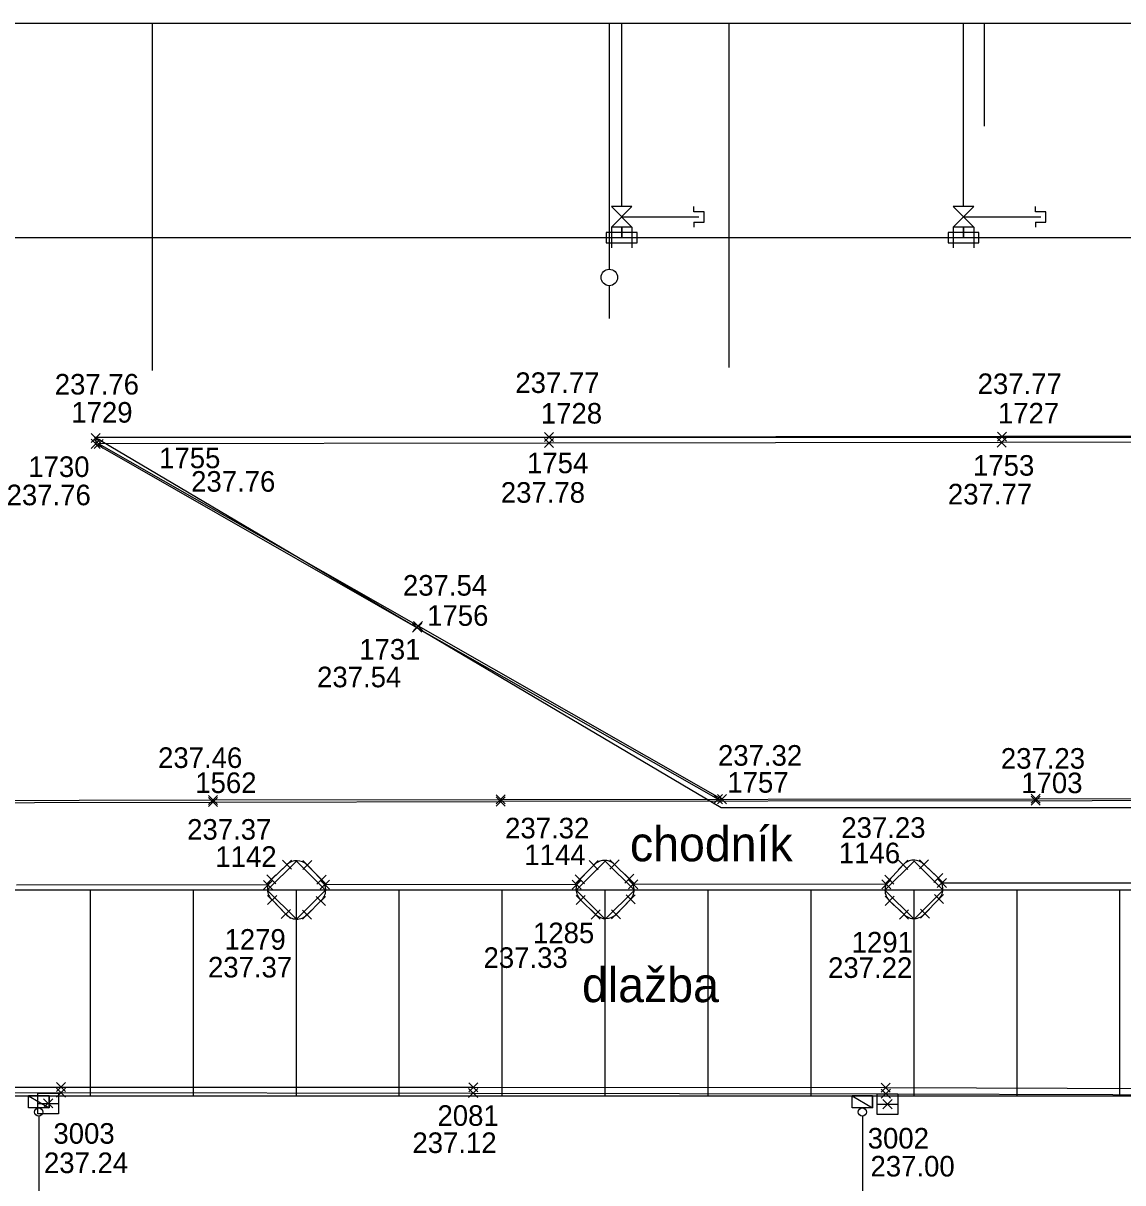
# Model space of a CAD drawing. Extents: x -264165 to -263733, y -1242319 to -1242245.
# Drawn here: x -263851.2 to -263824.5, y -1242273.09 to -1242244.94 of the extents above; entities that cross this region are included whole.
import ezdxf

# ---------------------------------------------------------------- set-up
doc = ezdxf.new("R2010")
doc.units = 0
for name, color, linetype in [('KFA_BOD_CISLO', 7, 'Continuous'), ('KFA_BOD_SYMBOL', 7, 'Continuous'), ('KFA_BOD_VYSKA', 7, 'Continuous'), ('KFA_SO_20-2_OBRUBNIKY_DOLNA_HRANA', 7, 'Continuous'), ('KFA_SO_20-2_OBRUBNIKY_HORNA_HRANA', 7, 'Continuous'), ('KFA_UV_BOD_CISLO', 7, 'Continuous'), ('KFA_UV_BOD_SYMBOL', 7, 'Continuous'), ('KFA_UV_BOD_VYSKA', 7, 'Continuous'), ('POPIS', 7, 'Continuous'), ('PROJEKT_OBRUBNIKY_KOMUNIKACIE', 7, 'Continuous'), ('PROJEKT_TDZ_VODOROVNE', 7, 'Continuous'), ('RAM_NA_TLAC_1-250', 7, 'Continuous'), ('SITUACIA_DSP_2D', 7, 'Continuous'), ('ULICNA_VPUST_POKLOP', 7, 'Continuous')]:
    doc.layers.add(name, color=color, linetype=linetype)

msp = doc.modelspace()

# ---------------------------------------------------------------- linework, layer by layer
at = {"layer": 'KFA_BOD_SYMBOL'}
for p, q in [((-263849.55, -1242255.261), (-263849.329, -1242255.039)), ((-263849.329, -1242255.261), (-263849.55, -1242255.039)), ((-263849.549, -1242255.116), (-263849.328, -1242254.894)), ((-263849.328, -1242255.116), (-263849.549, -1242254.894)), ((-263849.478, -1242255.262), (-263849.257, -1242255.042)), ((-263849.257, -1242255.262), (-263849.478, -1242255.042)), ((-263838.542, -1242255.093), (-263838.321, -1242254.873)), ((-263838.321, -1242255.093), (-263838.542, -1242254.873)), ((-263838.542, -1242255.241), (-263838.321, -1242255.019)), ((-263838.321, -1242255.241), (-263838.542, -1242255.019)), ((-263827.55, -1242255.228), (-263827.329, -1242255.007)), ((-263827.329, -1242255.228), (-263827.55, -1242255.007)), ((-263827.542, -1242255.083), (-263827.321, -1242254.862)), ((-263827.321, -1242255.083), (-263827.542, -1242254.862)), ((-263841.745, -1242259.725), (-263841.524, -1242259.504)), ((-263841.524, -1242259.725), (-263841.745, -1242259.504)), ((-263841.725, -1242259.681), (-263841.503, -1242259.461)), ((-263841.503, -1242259.681), (-263841.725, -1242259.461)), ((-263846.704, -1242263.907), (-263846.483, -1242263.687)), ((-263846.483, -1242263.907), (-263846.704, -1242263.687)), ((-263846.704, -1242263.958), (-263846.483, -1242263.737)), ((-263846.483, -1242263.958), (-263846.704, -1242263.737)), ((-263839.718, -1242263.894), (-263839.497, -1242263.674)), ((-263839.497, -1242263.894), (-263839.718, -1242263.674)), ((-263839.718, -1242263.944), (-263839.497, -1242263.724)), ((-263839.497, -1242263.944), (-263839.718, -1242263.724)), ((-263834.438, -1242263.887), (-263834.217, -1242263.666)), ((-263834.217, -1242263.887), (-263834.438, -1242263.666)), ((-263834.345, -1242263.887), (-263834.125, -1242263.666)), ((-263834.125, -1242263.887), (-263834.345, -1242263.666)), ((-263826.729, -1242263.924), (-263826.508, -1242263.704)), ((-263826.508, -1242263.924), (-263826.729, -1242263.704)), ((-263826.726, -1242263.876), (-263826.505, -1242263.654)), ((-263826.505, -1242263.876), (-263826.726, -1242263.654)), ((-263844.905, -1242265.475), (-263844.684, -1242265.255)), ((-263844.684, -1242265.475), (-263844.905, -1242265.255)), ((-263844.414, -1242265.488), (-263844.193, -1242265.266)), ((-263844.193, -1242265.488), (-263844.414, -1242265.266)), ((-263837.459, -1242265.49), (-263837.237, -1242265.269)), ((-263837.237, -1242265.49), (-263837.459, -1242265.269)), ((-263836.953, -1242265.474), (-263836.731, -1242265.252)), ((-263836.731, -1242265.474), (-263836.953, -1242265.252)), ((-263829.944, -1242265.481), (-263829.723, -1242265.261)), ((-263829.723, -1242265.481), (-263829.944, -1242265.261)), ((-263829.438, -1242265.471), (-263829.216, -1242265.251)), ((-263829.216, -1242265.471), (-263829.438, -1242265.251)), ((-263845.365, -1242265.968), (-263845.144, -1242265.748)), ((-263845.144, -1242265.968), (-263845.365, -1242265.748)), ((-263845.285, -1242265.836), (-263845.063, -1242265.615)), ((-263845.063, -1242265.836), (-263845.285, -1242265.615)), ((-263844.067, -1242265.84), (-263843.845, -1242265.619)), ((-263843.845, -1242265.84), (-263844.067, -1242265.619)), ((-263843.986, -1242265.965), (-263843.765, -1242265.745)), ((-263843.765, -1242265.965), (-263843.986, -1242265.745)), ((-263837.871, -1242265.961), (-263837.649, -1242265.741)), ((-263837.649, -1242265.961), (-263837.871, -1242265.741)), ((-263837.795, -1242265.833), (-263837.573, -1242265.613)), ((-263837.573, -1242265.833), (-263837.795, -1242265.613)), ((-263836.594, -1242265.819), (-263836.372, -1242265.599)), ((-263836.372, -1242265.819), (-263836.594, -1242265.599)), ((-263836.501, -1242265.958), (-263836.28, -1242265.738)), ((-263836.28, -1242265.958), (-263836.501, -1242265.738)), ((-263830.355, -1242265.954), (-263830.133, -1242265.732)), ((-263830.133, -1242265.954), (-263830.355, -1242265.732)), ((-263830.278, -1242265.843), (-263830.057, -1242265.622)), ((-263830.057, -1242265.843), (-263830.278, -1242265.622)), ((-263829.092, -1242265.799), (-263828.871, -1242265.578)), ((-263828.871, -1242265.799), (-263829.092, -1242265.578)), ((-263829.004, -1242265.924), (-263828.783, -1242265.704)), ((-263828.783, -1242265.924), (-263829.004, -1242265.704)), ((-263845.267, -1242266.335), (-263845.046, -1242266.113)), ((-263845.046, -1242266.335), (-263845.267, -1242266.113)), ((-263844.085, -1242266.357), (-263843.864, -1242266.137)), ((-263843.864, -1242266.357), (-263844.085, -1242266.137)), ((-263837.775, -1242266.333), (-263837.554, -1242266.113)), ((-263837.554, -1242266.333), (-263837.775, -1242266.113)), ((-263836.56, -1242266.319), (-263836.339, -1242266.097)), ((-263836.339, -1242266.319), (-263836.56, -1242266.097)), ((-263830.274, -1242266.356), (-263830.052, -1242266.134)), ((-263830.052, -1242266.356), (-263830.274, -1242266.134)), ((-263829.074, -1242266.312), (-263828.853, -1242266.09)), ((-263828.853, -1242266.312), (-263829.074, -1242266.09)), ((-263844.933, -1242266.678), (-263844.712, -1242266.458)), ((-263844.712, -1242266.678), (-263844.933, -1242266.458)), ((-263844.42, -1242266.693), (-263844.198, -1242266.471)), ((-263844.198, -1242266.693), (-263844.42, -1242266.471)), ((-263837.41, -1242266.688), (-263837.189, -1242266.468)), ((-263837.189, -1242266.688), (-263837.41, -1242266.468)), ((-263836.916, -1242266.684), (-263836.695, -1242266.464)), ((-263836.695, -1242266.684), (-263836.916, -1242266.464)), ((-263829.922, -1242266.687), (-263829.701, -1242266.465)), ((-263829.701, -1242266.687), (-263829.922, -1242266.465)), ((-263829.414, -1242266.664), (-263829.193, -1242266.444)), ((-263829.193, -1242266.664), (-263829.414, -1242266.444)), ((-263850.395, -1242271.014), (-263850.174, -1242270.792)), ((-263850.174, -1242271.014), (-263850.395, -1242270.792)), ((-263850.392, -1242270.877), (-263850.171, -1242270.656)), ((-263850.171, -1242270.877), (-263850.392, -1242270.656)), ((-263840.384, -1242271.024), (-263840.163, -1242270.802)), ((-263840.163, -1242271.024), (-263840.384, -1242270.802)), ((-263840.382, -1242270.883), (-263840.16, -1242270.661)), ((-263840.16, -1242270.883), (-263840.382, -1242270.661)), ((-263830.367, -1242270.893), (-263830.145, -1242270.671)), ((-263830.145, -1242270.893), (-263830.367, -1242270.671)), ((-263830.365, -1242271.039), (-263830.144, -1242270.819)), ((-263830.144, -1242271.039), (-263830.365, -1242270.819))]:
    msp.add_line(p, q, dxfattribs=at)
at = {"layer": 'KFA_SO_20-2_OBRUBNIKY_DOLNA_HRANA'}
for points in [[(-263870.268, -1242270.778), (-263860.244, -1242270.766), (-263850.281, -1242270.766), (-263840.271, -1242270.772), (-263830.256, -1242270.782), (-263819.239, -1242270.817)], [(-263870.27, -1242270.923), (-263860.247, -1242270.914), (-263850.285, -1242270.903), (-263840.274, -1242270.913), (-263830.254, -1242270.929), (-263819.233, -1242270.965)]]:
    msp.add_lwpolyline(points, dxfattribs=at)
at = {"layer": 'KFA_SO_20-2_OBRUBNIKY_HORNA_HRANA'}
for p, q in [((-263839.607, -1242263.784), (-263826.616, -1242263.765)), ((-263826.616, -1242263.765), (-263822.618, -1242263.754)), ((-263826.618, -1242263.814), (-263839.607, -1242263.834)), ((-263826.618, -1242263.814), (-263822.617, -1242263.795)), ((-263845.174, -1242265.725), (-263844.795, -1242265.365)), ((-263844.303, -1242265.377), (-263843.956, -1242265.729)), ((-263837.684, -1242265.723), (-263837.348, -1242265.379)), ((-263836.483, -1242265.709), (-263836.842, -1242265.363)), ((-263830.167, -1242265.732), (-263829.834, -1242265.371)), ((-263829.327, -1242265.361), (-263828.981, -1242265.688)), ((-263845.254, -1242265.858), (-263851.364, -1242265.868)), ((-263837.76, -1242265.851), (-263843.876, -1242265.855)), ((-263830.244, -1242265.843), (-263836.39, -1242265.848)), ((-263822.6, -1242265.815), (-263828.894, -1242265.814)), ((-263844.823, -1242266.568), (-263845.156, -1242266.224)), ((-263843.975, -1242266.247), (-263844.309, -1242266.582)), ((-263837.665, -1242266.223), (-263837.3, -1242266.578)), ((-263836.806, -1242266.574), (-263836.449, -1242266.208)), ((-263829.812, -1242266.576), (-263830.163, -1242266.245)), ((-263828.964, -1242266.201), (-263829.303, -1242266.554))]:
    msp.add_line(p, q, dxfattribs=at)
for points in [[(-263802.049, -1242254.926), (-263813.428, -1242254.951), (-263827.432, -1242254.972), (-263838.432, -1242254.983), (-263849.438, -1242255.005), (-263849.439, -1242255.15), (-263841.634, -1242259.614), (-263834.328, -1242263.776)], [(-263802.192, -1242255.074), (-263813.429, -1242255.098), (-263827.439, -1242255.117), (-263838.432, -1242255.13), (-263849.367, -1242255.152), (-263841.614, -1242259.571), (-263834.235, -1242263.776)], [(-263909.527, -1242263.897), (-263899.537, -1242263.895), (-263889.544, -1242263.882), (-263879.556, -1242263.864), (-263869.563, -1242263.857), (-263859.593, -1242263.827), (-263846.594, -1242263.797), (-263839.607, -1242263.784)], [(-263909.527, -1242263.947), (-263899.537, -1242263.945), (-263889.544, -1242263.932), (-263879.556, -1242263.914), (-263869.563, -1242263.907), (-263859.593, -1242263.877), (-263846.594, -1242263.847), (-263839.607, -1242263.834)]]:
    msp.add_lwpolyline(points, dxfattribs=at)
for centre, major_axis, ratio, start_param, end_param in [((-263844.555, -1242265.625), (-0.353, 0.033), 0.998197, 4.012394, 5.547908), ((-263837.087, -1242265.615), (-0.326, -0.134), 0.999936, 3.551655, 5.156884), ((-263829.576, -1242265.607), (-0.346, 0.052), 0.998302, 4.072697, 5.692261), ((-263844.925, -1242265.966), (-0.275, -0.211), 0.999634, 4.858507, 6.470204), ((-263844.209, -1242265.979), (0.065, 0.35), 0.999654, 4.043218, 5.6761), ((-263837.425, -1242265.964), (0.248, -0.252), 0.999842, 3.187032, 4.758259), ((-263836.732, -1242265.977), (-0.155, 0.331), 0.999985, 3.589625, 5.096185), ((-263829.918, -1242265.987), (-0.226, -0.276), 0.999926, 4.603012, 6.210751), ((-263829.231, -1242265.953), (-0.033, 0.363), 0.99945, 3.87257, 5.43466), ((-263844.56, -1242266.343), (0.151, 0.311), 0.999672, 2.729443, 4.403752), ((-263837.055, -1242266.322), (0.263, 0.238), 0.999704, 3.213048, 4.755576), ((-263829.568, -1242266.325), (0.35, 0.015), 0.999834, 3.897217, 5.527561)]:
    msp.add_ellipse(centre, major_axis=major_axis, ratio=ratio, start_param=start_param, end_param=end_param, dxfattribs=at)
at = {"layer": 'KFA_UV_BOD_SYMBOL'}
for p, q in [((-263850.704, -1242271.275), (-263850.483, -1242271.053)), ((-263850.483, -1242271.275), (-263850.704, -1242271.053)), ((-263830.324, -1242271.293), (-263830.103, -1242271.073)), ((-263830.103, -1242271.293), (-263830.324, -1242271.073))]:
    msp.add_line(p, q, dxfattribs=at)
at = {"layer": 'PROJEKT_OBRUBNIKY_KOMUNIKACIE'}
for p, q in [((-263807.068, -1242265.987), (-263917.08, -1242265.983)), ((-263917.578, -1242270.983), (-263807.068, -1242270.982))]:
    msp.add_line(p, q, dxfattribs=at)
for points in [[(-263802.068, -1242263.988), (-263834.256, -1242263.984), (-263849.468, -1242254.985), (-263802.068, -1242254.987), (-263802.068, -1242263.988)], [(-263844.568, -1242265.279), (-263843.861, -1242265.986), (-263844.568, -1242266.694), (-263845.275, -1242265.986), (-263844.568, -1242265.279)], [(-263837.068, -1242265.279), (-263836.361, -1242265.986), (-263837.068, -1242266.694), (-263837.775, -1242265.986), (-263837.068, -1242265.279)], [(-263829.568, -1242265.279), (-263828.861, -1242265.986), (-263829.568, -1242266.694), (-263830.275, -1242265.986), (-263829.568, -1242265.279)]]:
    msp.add_lwpolyline(points, dxfattribs=at)
at = {"layer": 'PROJEKT_TDZ_VODOROVNE'}
for p, q in [((-263849.568, -1242270.982), (-263849.568, -1242265.982)), ((-263847.068, -1242270.982), (-263847.068, -1242265.982)), ((-263844.568, -1242270.982), (-263844.568, -1242265.982)), ((-263842.068, -1242270.982), (-263842.068, -1242265.982)), ((-263839.568, -1242270.982), (-263839.568, -1242265.982)), ((-263837.068, -1242270.982), (-263837.068, -1242265.982)), ((-263834.568, -1242270.982), (-263834.568, -1242265.982)), ((-263832.068, -1242270.982), (-263832.068, -1242265.982)), ((-263829.568, -1242270.982), (-263829.568, -1242265.982)), ((-263827.068, -1242270.982), (-263827.068, -1242265.982)), ((-263824.568, -1242270.982), (-263824.568, -1242265.982))]:
    msp.add_line(p, q, dxfattribs=at)
at = {"layer": 'RAM_NA_TLAC_1-250'}
msp.add_line((-263827.863, -1242244.935), (-263827.863, -1242247.435), dxfattribs=at)
msp.add_lwpolyline([(-264165.363, -1242244.935), (-263732.863, -1242244.935), (-263732.863, -1242319.185), (-264165.363, -1242319.185)], close=True, dxfattribs=at)
at = {"layer": 'SITUACIA_DSP_2D'}
for p, q in [((-263848.068, -1242244.935), (-263848.068, -1242253.366)), ((-263836.969, -1242244.935), (-263836.969, -1242250.909)), ((-263836.668, -1242249.39), (-263836.668, -1242244.935)), ((-263834.068, -1242244.935), (-263834.068, -1242253.298)), ((-263828.368, -1242249.39), (-263828.368, -1242244.935)), ((-263836.418, -1242249.39), (-263836.918, -1242249.39)), ((-263836.918, -1242249.89), (-263836.418, -1242249.39)), ((-263836.918, -1242249.39), (-263836.418, -1242249.89)), ((-263834.918, -1242249.515), (-263834.918, -1242249.39)), ((-263828.118, -1242249.39), (-263828.618, -1242249.39)), ((-263828.618, -1242249.89), (-263828.118, -1242249.39)), ((-263828.618, -1242249.39), (-263828.118, -1242249.89)), ((-263826.618, -1242249.515), (-263826.618, -1242249.39)), ((-263836.668, -1242249.64), (-263834.793, -1242249.64)), ((-263834.668, -1242249.515), (-263834.918, -1242249.515)), ((-263834.668, -1242249.765), (-263834.668, -1242249.515)), ((-263828.368, -1242249.64), (-263826.493, -1242249.64)), ((-263826.368, -1242249.515), (-263826.618, -1242249.515)), ((-263826.368, -1242249.765), (-263826.368, -1242249.515)), ((-263836.418, -1242249.89), (-263836.918, -1242249.89)), ((-263836.918, -1242249.89), (-263836.918, -1242250.39)), ((-263836.668, -1242250.14), (-263836.668, -1242249.89)), ((-263836.668, -1242249.89), (-263836.668, -1242250.14)), ((-263836.418, -1242249.89), (-263836.418, -1242250.39)), ((-263834.918, -1242249.765), (-263834.918, -1242249.89)), ((-263834.918, -1242249.765), (-263834.668, -1242249.765)), ((-263828.118, -1242249.89), (-263828.618, -1242249.89)), ((-263828.618, -1242249.89), (-263828.618, -1242250.39)), ((-263828.368, -1242250.14), (-263828.368, -1242249.89)), ((-263828.368, -1242249.89), (-263828.368, -1242250.14)), ((-263828.118, -1242249.89), (-263828.118, -1242250.39)), ((-263826.618, -1242249.765), (-263826.618, -1242249.89)), ((-263826.618, -1242249.765), (-263826.368, -1242249.765)), ((-263924.143, -1242250.14), (-263788.143, -1242250.14)), ((-263836.293, -1242250.015), (-263837.043, -1242250.015)), ((-263837.043, -1242250.015), (-263837.043, -1242250.265)), ((-263837.043, -1242250.265), (-263836.293, -1242250.265)), ((-263836.293, -1242250.265), (-263836.293, -1242250.015)), ((-263827.993, -1242250.015), (-263828.743, -1242250.015)), ((-263828.743, -1242250.015), (-263828.743, -1242250.265)), ((-263828.743, -1242250.265), (-263827.993, -1242250.265)), ((-263827.993, -1242250.265), (-263827.993, -1242250.015)), ((-263836.969, -1242251.309), (-263836.969, -1242252.109)), ((-263851.074, -1242270.983), (-263850.574, -1242270.983)), ((-263851.074, -1242271.273), (-263851.074, -1242270.983)), ((-263851.074, -1242270.983), (-263850.574, -1242271.273)), ((-263851.074, -1242270.983), (-263850.574, -1242271.273)), ((-263850.574, -1242270.983), (-263851.074, -1242270.983)), ((-263850.574, -1242270.983), (-263850.574, -1242271.273)), ((-263850.574, -1242271.273), (-263850.574, -1242270.983)), ((-263831.074, -1242270.983), (-263830.574, -1242270.983)), ((-263831.074, -1242271.273), (-263831.074, -1242270.983)), ((-263831.074, -1242270.983), (-263830.574, -1242271.273)), ((-263831.074, -1242270.983), (-263830.574, -1242271.273)), ((-263830.574, -1242270.983), (-263831.074, -1242270.983)), ((-263830.574, -1242270.983), (-263830.574, -1242271.273)), ((-263830.574, -1242271.273), (-263830.574, -1242270.983)), ((-263850.574, -1242271.273), (-263851.074, -1242271.273)), ((-263830.574, -1242271.273), (-263831.074, -1242271.273)), ((-263850.824, -1242271.473), (-263850.824, -1242283.187)), ((-263830.824, -1242271.473), (-263830.824, -1242283.187))]:
    msp.add_line(p, q, dxfattribs=at)
for points in [[(-263802.068, -1242263.988), (-263834.256, -1242263.984), (-263849.468, -1242254.985), (-263802.068, -1242254.987)], [(-263844.568, -1242265.279), (-263843.861, -1242265.986), (-263844.568, -1242266.693), (-263845.275, -1242265.986)], [(-263837.068, -1242265.279), (-263836.361, -1242265.986), (-263837.068, -1242266.693), (-263837.775, -1242265.986)], [(-263829.568, -1242265.279), (-263828.861, -1242265.986), (-263829.568, -1242266.693), (-263830.275, -1242265.986)]]:
    msp.add_lwpolyline(points, close=True, dxfattribs=at)
for centre, radius in [((-263836.969, -1242251.109), 0.2), ((-263850.824, -1242271.373), 0.1), ((-263830.824, -1242271.373), 0.1)]:
    msp.add_circle(centre, radius, dxfattribs=at)
at = {"layer": 'ULICNA_VPUST_POKLOP'}
for p, q in [((-263850.594, -1242271.164), (-263850.594, -1242271.164)), ((-263830.214, -1242271.183), (-263830.214, -1242271.183))]:
    msp.add_line(p, q, dxfattribs=at)
for points in [[(-263850.844, -1242271.164), (-263850.844, -1242270.914), (-263850.344, -1242270.914), (-263850.344, -1242271.414), (-263850.844, -1242271.414), (-263850.844, -1242271.164), (-263850.344, -1242271.164)], [(-263830.464, -1242271.183), (-263830.464, -1242270.933), (-263829.964, -1242270.933), (-263829.964, -1242271.433), (-263830.464, -1242271.433), (-263830.464, -1242271.183), (-263829.964, -1242271.183)]]:
    msp.add_lwpolyline(points, dxfattribs=at)

# ---------------------------------------------------------------- texts
at = {"layer": 'KFA_BOD_CISLO'}
for s, p in [('1729', (-263850.033, -1242254.634)), ('1728', (-263838.631, -1242254.657)), ('1727', (-263827.532, -1242254.655)), ('1755', (-263847.9, -1242255.741)), ('1730', (-263851.077, -1242255.954)), ('1754', (-263838.966, -1242255.862)), ('1753', (-263828.136, -1242255.923)), ('1756', (-263841.392, -1242259.567)), ('1731', (-263843.041, -1242260.387)), ('1562', (-263847.022, -1242263.628)), ('1757', (-263834.102, -1242263.62)), ('1703', (-263826.966, -1242263.631)), ('1144', (-263839.031, -1242265.379)), ('1146', (-263831.395, -1242265.333)), ('1142', (-263846.534, -1242265.42)), ('1285', (-263838.822, -1242267.274)), ('1279', (-263846.312, -1242267.432)), ('1291', (-263831.084, -1242267.5)), ('2081', (-263841.141, -1242271.709))]:
    msp.add_text(s, height=0.5, dxfattribs=at).set_placement(p)
at = {"layer": 'KFA_BOD_VYSKA'}
for s, p in [('237.76', (-263850.434, -1242253.952)), ('237.77', (-263839.251, -1242253.914)), ('237.77', (-263828.025, -1242253.94)), ('237.76', (-263847.123, -1242256.311)), ('237.76', (-263851.604, -1242256.64)), ('237.78', (-263839.603, -1242256.579)), ('237.77', (-263828.747, -1242256.62)), ('237.54', (-263841.98, -1242258.835)), ('237.54', (-263844.065, -1242261.06)), ('237.46', (-263847.926, -1242263.019)), ('237.32', (-263834.33, -1242262.964)), ('237.23', (-263827.461, -1242263.037)), ('237.37', (-263847.22, -1242264.761)), ('237.32', (-263839.499, -1242264.729)), ('237.23', (-263831.335, -1242264.716)), ('237.33', (-263840.023, -1242267.874)), ('237.37', (-263846.714, -1242268.106)), ('237.22', (-263831.657, -1242268.117)), ('237.12', (-263841.75, -1242272.369))]:
    msp.add_text(s, height=0.5, dxfattribs=at).set_placement(p)
at = {"layer": 'KFA_UV_BOD_CISLO'}
for s, p in [('3003', (-263850.467, -1242272.143)), ('3002', (-263830.694, -1242272.26))]:
    msp.add_text(s, height=0.5, dxfattribs=at).set_placement(p)
at = {"layer": 'KFA_UV_BOD_VYSKA'}
for s, p in [('237.24', (-263850.697, -1242272.856)), ('237.00', (-263830.627, -1242272.939))]:
    msp.add_text(s, height=0.5, dxfattribs=at).set_placement(p)
at = {"layer": 'POPIS'}
for s, p in [('chodník', (-263836.468, -1242265.285)), ('dlažba', (-263837.631, -1242268.705))]:
    msp.add_text(s, height=0.8438, dxfattribs=at).set_placement(p)

doc.saveas('drawing.dxf')
